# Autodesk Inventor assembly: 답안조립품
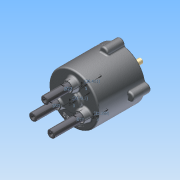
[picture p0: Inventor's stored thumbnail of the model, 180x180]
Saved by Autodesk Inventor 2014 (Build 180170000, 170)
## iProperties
Created: 2015-09
Part Number: 답안조립품
Document SubType Name: Assembly
Designer: study
Mass: 500.894 g
Surface Area: 1801.25 cm^2
Volume: 438.509 cm^3
Density: 1.14226 g/cm^3
Author: study
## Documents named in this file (14)
- C:\Users\study\Desktop\350916V1005\답안조립품.iam
- C:\Users\study\Desktop\350916V1005\몸체.ipt
- C:\Users\study\Desktop\350916V1005\커버.ipt
- C:\Users\study\Desktop\350916V1005\베어링 NA 4900.ipt
- C:\Users\study\Desktop\350916V1005\오일실.ipt
- C:\Users\study\Desktop\350916V1005\M5x0.8x20.ipt
- C:\Users\study\Desktop\350916V1005\메인 축.ipt
- C:\Users\study\Desktop\350916V1005\멈춤링 22 x 1.2.ipt
- C:\Users\study\Desktop\350916V1005\멈춤링 10 x 1.ipt
- C:\Users\study\Desktop\350916V1005\판캠.ipt
- C:\Users\study\Desktop\350916V1005\슬라이드 축.ipt
- C:\Users\study\Desktop\350916V1005\11-가변 스프링.ipt
- C:\Users\study\Desktop\350916V1005\12-가변 스프링.ipt
- C:\Users\study\Desktop\350916V1005\13-가변 스프링.ipt
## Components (7 placed, 4 different names)
1. 11-가변 스프링:1
2. 12-가변 스프링:1
3. 13-가변 스프링:1
4. M5x0.8x20:1
5. M5x0.8x20:2
6. M5x0.8x20:3
7. M5x0.8x20:4
